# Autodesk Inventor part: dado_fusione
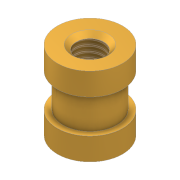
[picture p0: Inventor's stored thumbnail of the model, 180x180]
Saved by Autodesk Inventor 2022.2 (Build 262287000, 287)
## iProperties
Created: 2025-03
Part Number: dado_fusione
Material: Ottone, Giallo chiaro
Document SubType Name: Modeling
Designer: 18907419
Density: 8.47 g/cm^3
Appearance: Ottone - Satinato
Author: 18907419
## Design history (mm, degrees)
sketch "Schizzo1"
  geometry: L1 (0, 0)-(2.9, 0); L2 (2.9, 0)-(2.9, 2); L3 (2.9, 2)-(2.4, 2); L4 (2.4, 2)-(2.4, 5); L5 (2.4, 5)-(2.9, 5); L6 (2.9, 5)-(2.9, 7); L7 (2.9, 7)-(0, 7); L8 (0, 7)-(0, 0)
  constraints: 16 end point, 5 perpendicular, 2 point on line
  dimensions: "d0" = 2.9 distance of L1.start L1.end; "d1" = 2 distance of L1.end L2.end; "d2" = 0.5 distance of L2.end L3.end; "d3" = 3 distance of L3.end L4.end; "d4" = 2 distance of L5.end L6.end
revolve "Rivoluzione1" sketch "Schizzo1" stored, may be unused: angle "d5" = 90 deg
sketch "Schizzo2"
  geometry: C1 r 2.9 at (0, 0) reference; 2 further points
  constraints: 1 coincident
hole "Foro1" sketch "Schizzo2" at (0, 0) diameter "d6" = 2.459; stored, may be unused: countersink angle "d10" = 90 deg, drill point angle "d12" = 0 deg; dims "d7" = 6, "d8" = 11, "d9" = 2.6, "d11" = 8.8
chamfer "Smusso1" distance "d13" = 0.4; stored, may be unused: second distance "d14" = 2, angle "d15" = 45 deg
node "Solido1"
